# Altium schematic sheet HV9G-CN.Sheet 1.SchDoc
size 431 x 279 mm
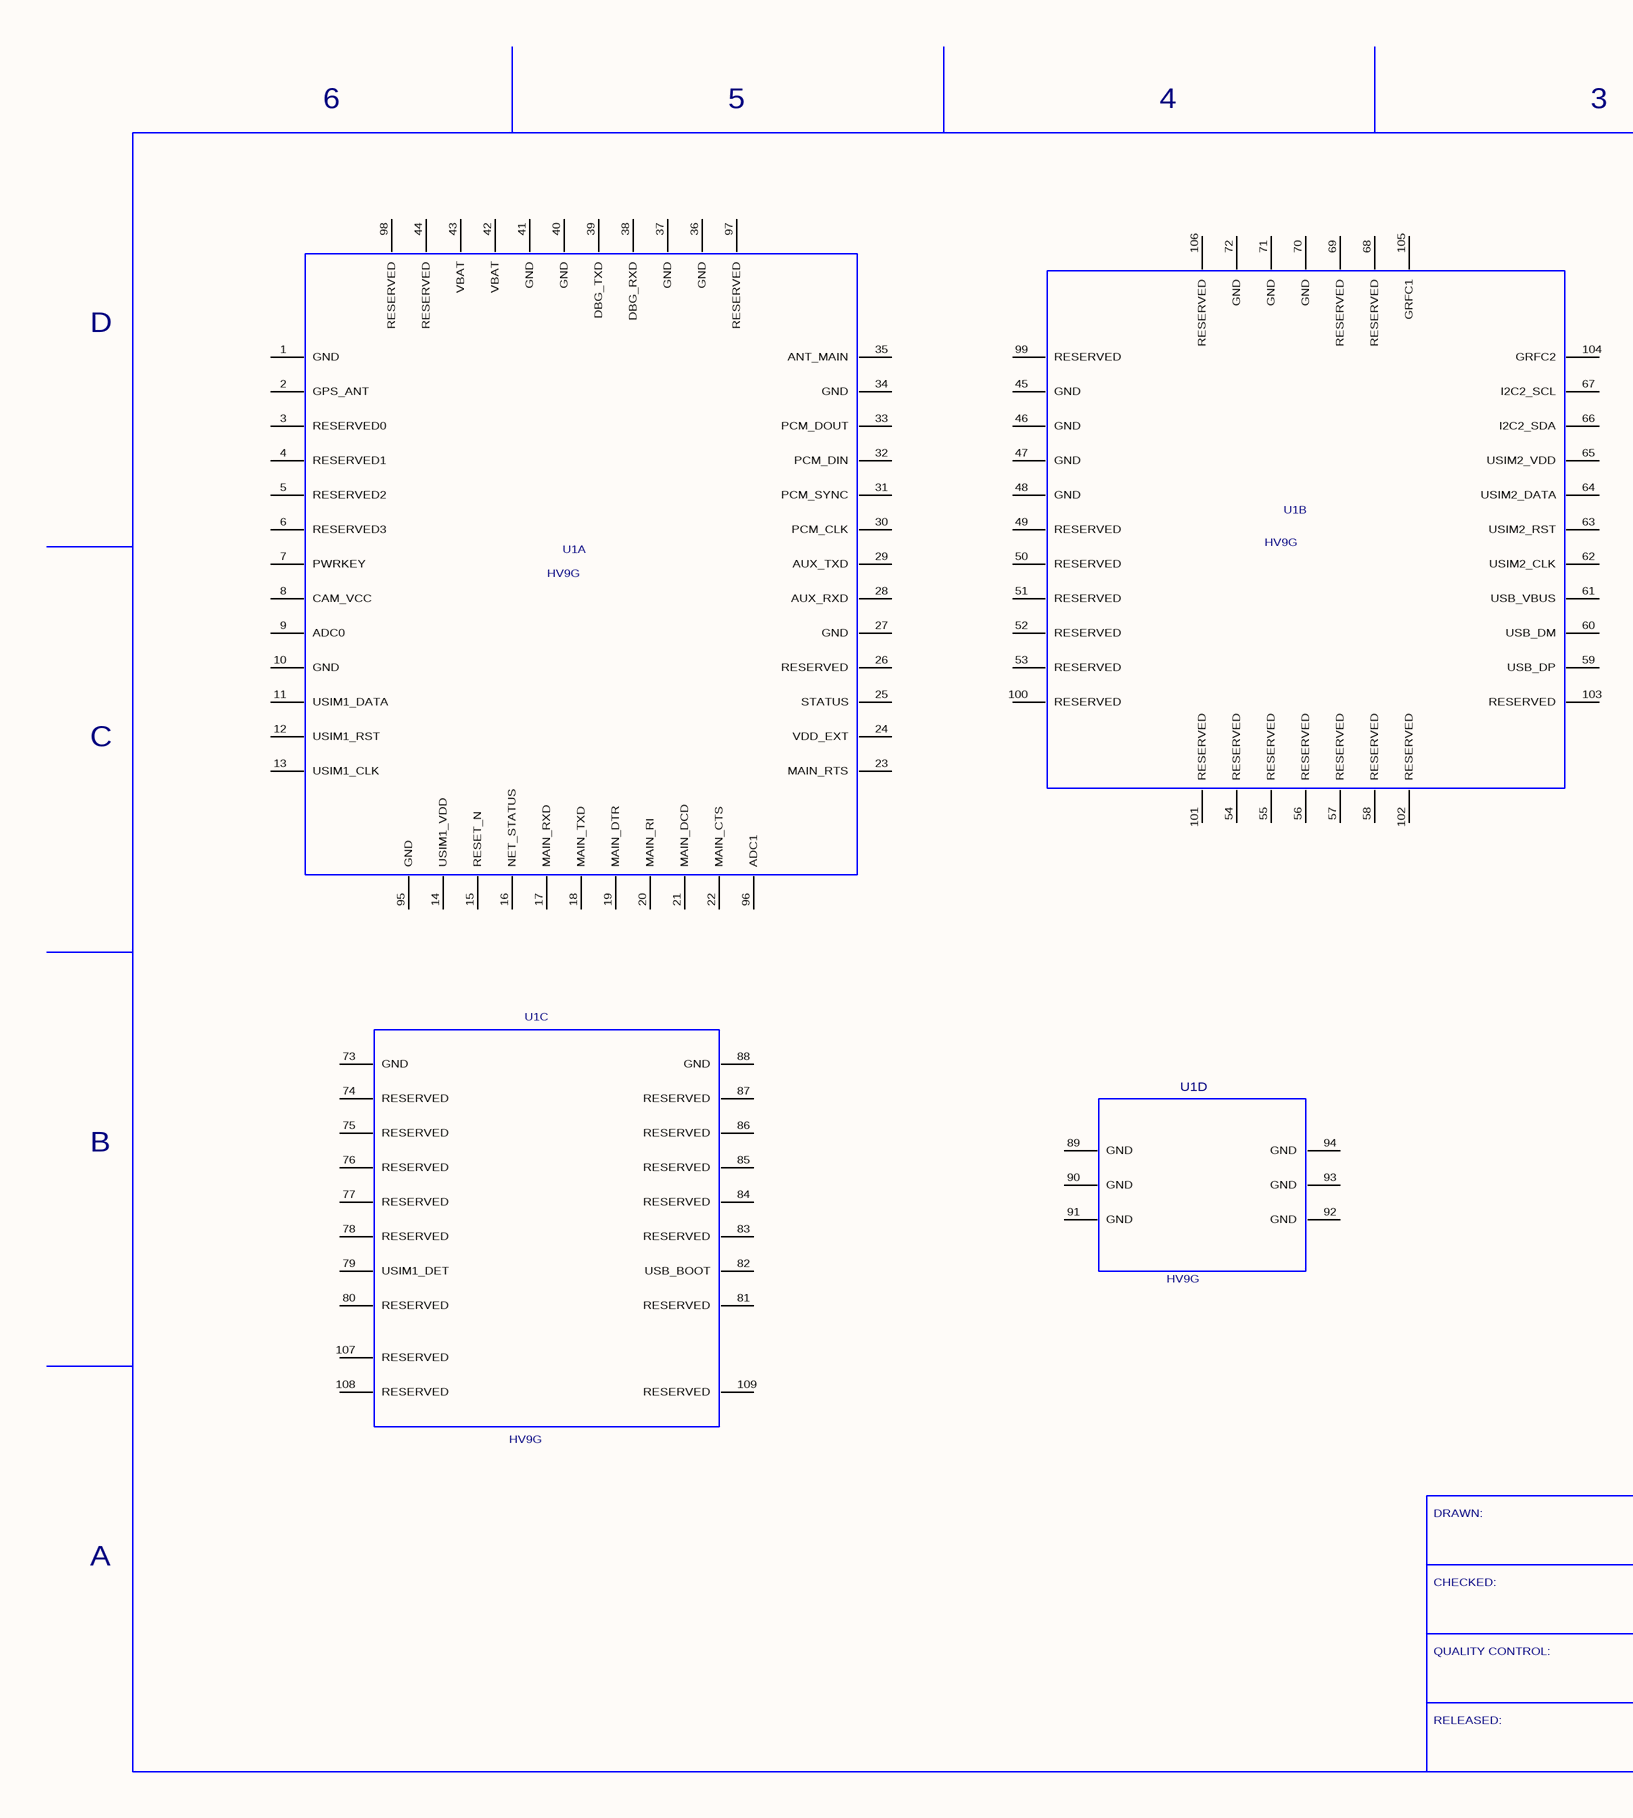
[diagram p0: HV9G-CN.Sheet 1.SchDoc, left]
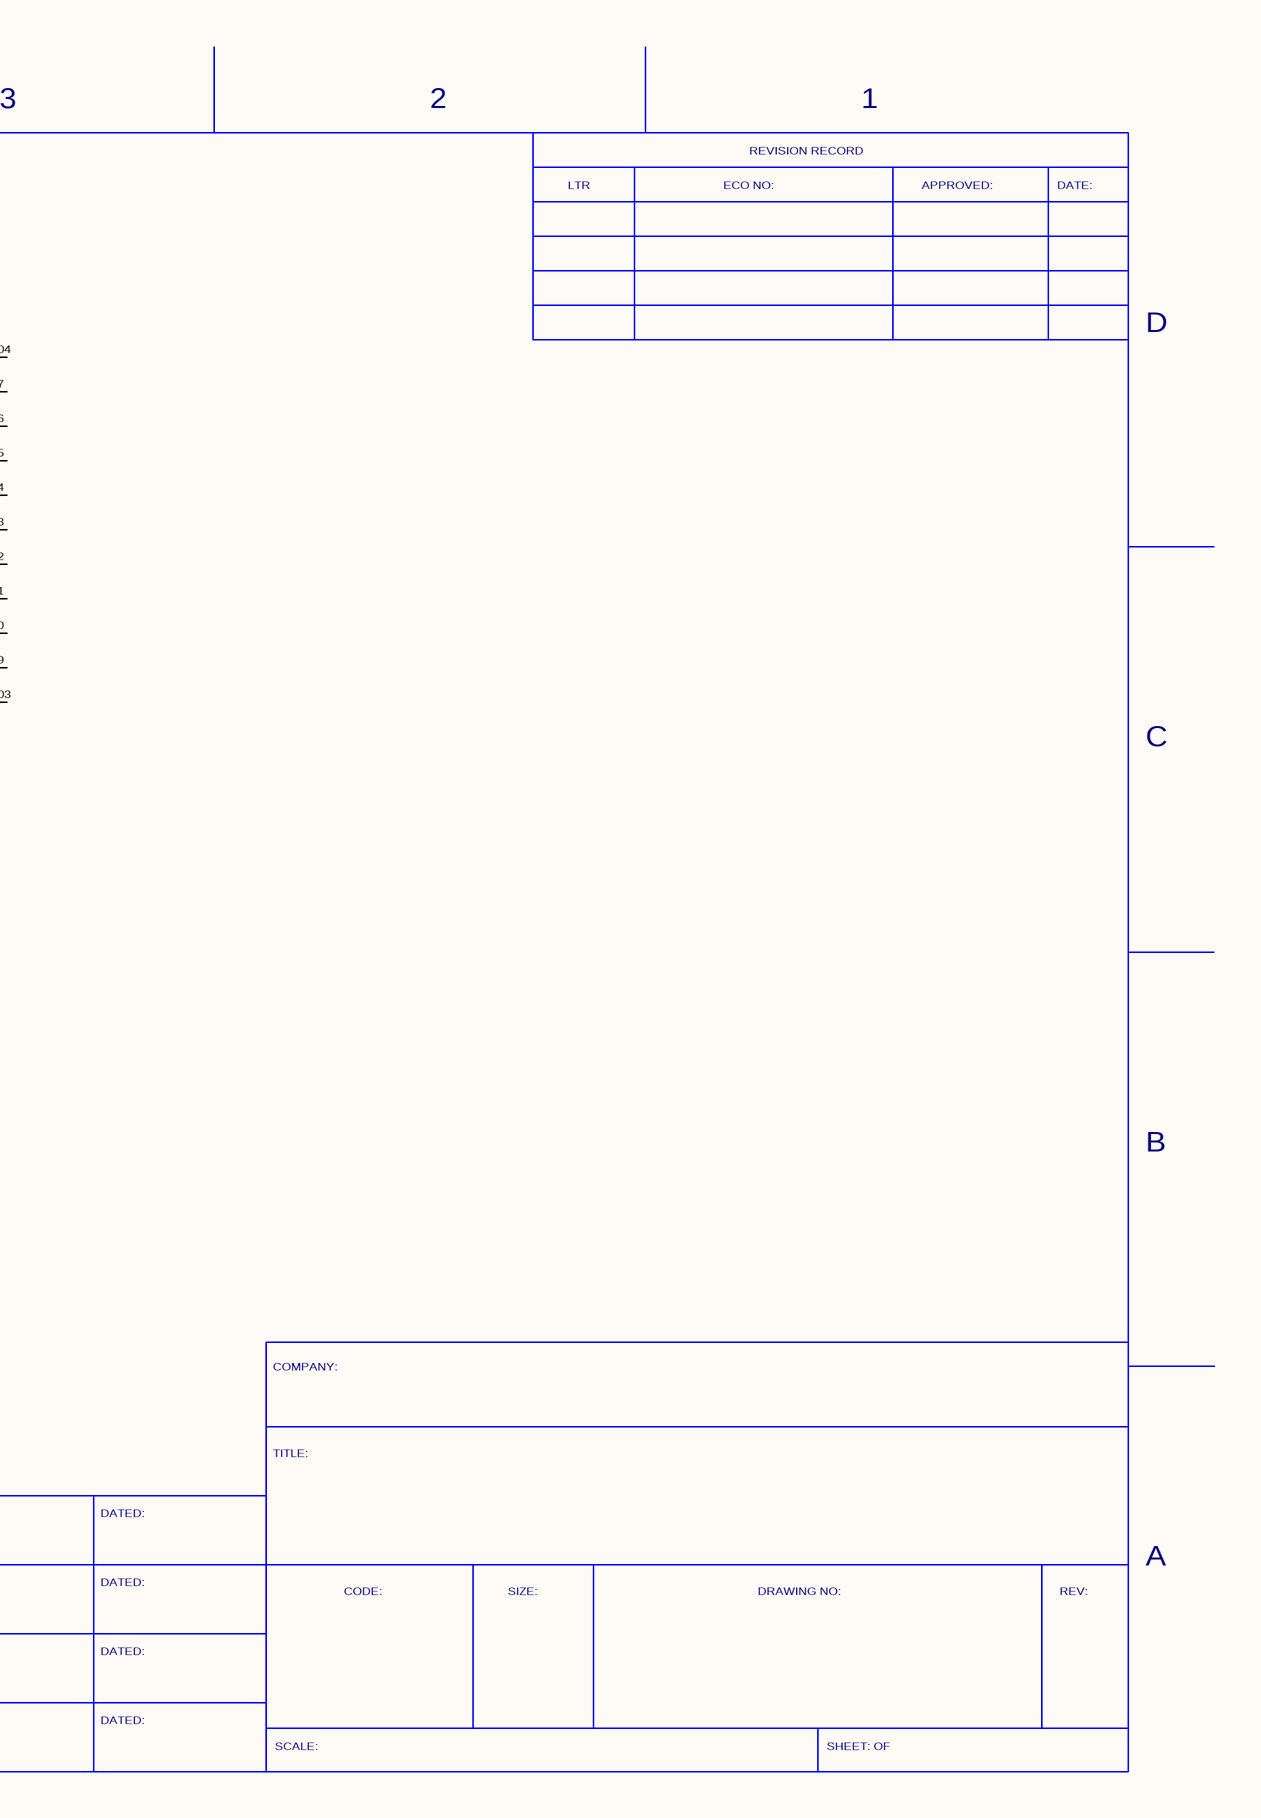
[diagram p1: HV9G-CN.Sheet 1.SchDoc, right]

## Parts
U1  HV9G  [HV9G]  (parts A,B,C,D of 4)

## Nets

Not connected (* = marked no-connect by the designer): U1 1(GND) 2(GPS_ANT) 3(RESERVED0) 4(RESERVED1) 5(RESERVED2) 6(RESERVED3) 7(PWRKEY) 8(CAM_VCC) 9(ADC0) 10(GND) 11(USIM1_DATA) 12(USIM1_RST) 13(USIM1_CLK) 14(USIM1_VDD) 15(RESET_N) 16(NET_STATUS) 17(MAIN_RXD) 18(MAIN_TXD) 19(MAIN_DTR) 20(MAIN_RI) 21(MAIN_DCD) 22(MAIN_CTS) 23(MAIN_RTS) 24(VDD_EXT) 25(STATUS) 26(RESERVED) 27(GND) 28(AUX_RXD) 29(AUX_TXD) 30(PCM_CLK) 31(PCM_SYNC) 32(PCM_DIN) 33(PCM_DOUT) 34(GND) 35(ANT_MAIN) 36(GND) 37(GND) 38(DBG_RXD) 39(DBG_TXD) 40(GND) 41(GND) 42(VBAT) 43(VBAT) 44(RESERVED) 45(GND) 46(GND) 47(GND) 48(GND) 49(RESERVED) 50(RESERVED) 51(RESERVED) 52(RESERVED) 53(RESERVED) 54(RESERVED) 55(RESERVED) 56(RESERVED) 57(RESERVED) 58(RESERVED) 59(USB_DP) 60(USB_DM) 61(USB_VBUS) 62(USIM2_CLK) 63(USIM2_RST) 64(USIM2_DATA) 65(USIM2_VDD) 66(I2C2_SDA) 67(I2C2_SCL) 68(RESERVED) 69(RESERVED) 70(GND) 71(GND) 72(GND) 73(GND) 74(RESERVED) 75(RESERVED) 76(RESERVED) 77(RESERVED) 78(RESERVED) 79(USIM1_DET) 80(RESERVED) 81(RESERVED) 82(USB_BOOT) 83(RESERVED) 84(RESERVED) 85(RESERVED) 86(RESERVED) 87(RESERVED) 88(GND) 89(GND) 90(GND) 91(GND) 92(GND) 93(GND) 94(GND) 95(GND) 96(ADC1) 97(RESERVED) 98(RESERVED) 99(RESERVED) 100(RESERVED) 101(RESERVED) 102(RESERVED) 103(RESERVED) 104(GRFC2) 105(GRFC1) 106(RESERVED) 107(RESERVED) 108(RESERVED) 109(RESERVED)

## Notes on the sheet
- 6
- 5
- 4
- 3
- 2
- REVISION RECORD
- 1
- LTR
- ECO NO:
- APPROVED:
- DATE:
- D
- C
- B
- COMPANY:
- TITLE:
- DRAWN:
- DATED:
- A
- CHECKED:
- CODE:
- SIZE:
- DRAWING NO:
- REV:
- QUALITY CONTROL:
- RELEASED:
- SCALE:
- SHEET: OF

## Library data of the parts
U1 = HV9G: Manufacturer: Quectel; Part_Description: HV9G Moudle 109PIN 15.8X17.7mm H2.4mm RO; Geometry_Height: 2.4mm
